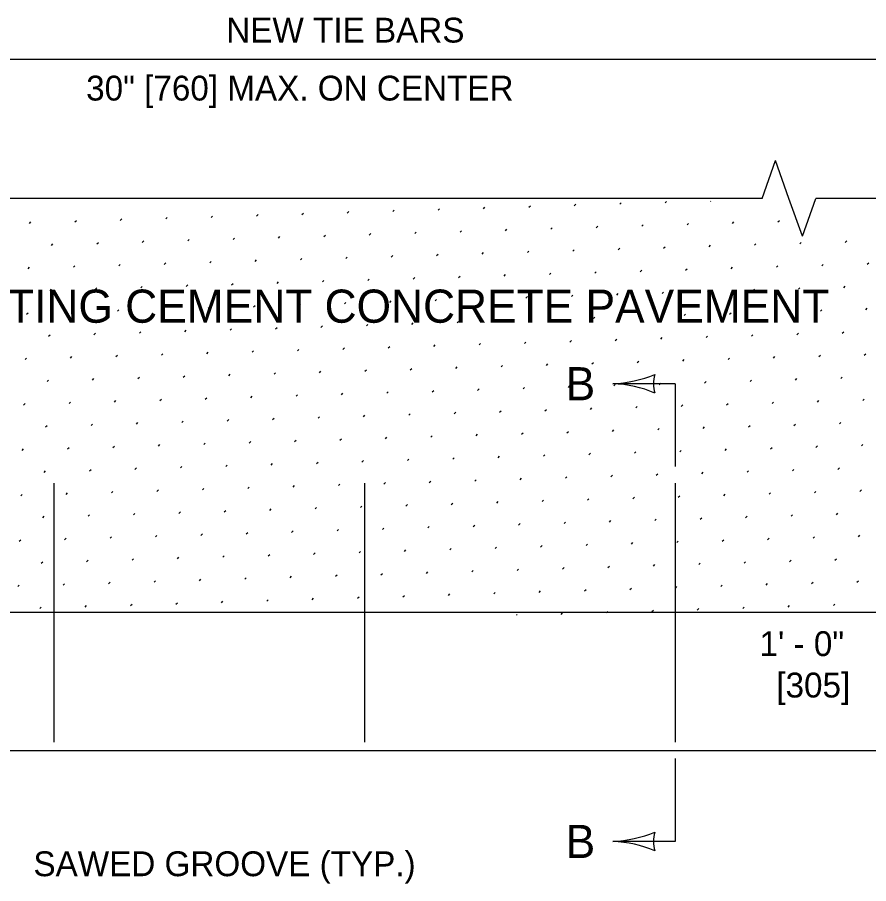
# Model space of a CAD drawing. Extents: x 49991.4 to 50021, y 49987.6 to 50011.4.
# Drawn here: x 50003.394 to 50005.45, y 49991.149 to 49993.241 of the extents above; entities that cross this region are included whole.
import ezdxf

# ---------------------------------------------------------------- set-up
doc = ezdxf.new("R2010")
doc.units = 0
for name, color, linetype in [('Level 1', 7, 'Continuous'), ('Level 10', 7, 'Continuous'), ('Level 2', 7, 'Continuous'), ('Level 3', 7, 'Continuous'), ('Level 4', 7, 'Continuous'), ('Level 6', 7, 'Continuous')]:
    doc.layers.add(name, color=color, linetype=linetype)

msp = doc.modelspace()

# ---------------------------------------------------------------- linework, layer by layer
at = {"layer": 'Level 1'}
for p, q in [((50006.1071, 49991.8039), (50002.3571, 49991.8039)), ((50002.6071, 49991.4706), (50005.8571, 49991.4706))]:
    msp.add_line(p, q, dxfattribs=at)
at = {"layer": 'Level 10'}
for p, q in [((50004.9581, 49992.793), (50004.9616, 49992.7966)), ((50005.0677, 49992.7966), (50005.0686, 49992.7974)), ((50004.3005, 49992.7718), (50004.304, 49992.7753)), ((50004.4101, 49992.7753), (50004.4136, 49992.7788)), ((50004.5197, 49992.7789), (50004.5232, 49992.7824)), ((50004.6293, 49992.7824), (50004.6328, 49992.7859)), ((50004.7389, 49992.7859), (50004.7424, 49992.7895)), ((50004.8485, 49992.7895), (50004.852, 49992.793)), ((50003.6428, 49992.7505), (50003.6463, 49992.7541)), ((50003.7524, 49992.7541), (50003.7559, 49992.7576)), ((50003.862, 49992.7576), (50003.8656, 49992.7611)), ((50003.9716, 49992.7611), (50003.9752, 49992.7647)), ((50004.0812, 49992.7647), (50004.0848, 49992.7682)), ((50004.1908, 49992.7682), (50004.1944, 49992.7718)), ((50003.4236, 49992.7434), (50003.4271, 49992.747)), ((50003.5332, 49992.747), (50003.5367, 49992.7505)), ((50004.7919, 49992.7329), (50004.7955, 49992.7364)), ((50004.9015, 49992.7365), (50004.9051, 49992.74)), ((50005.0111, 49992.74), (50005.0147, 49992.7435)), ((50005.1207, 49992.7435), (50005.1243, 49992.7471)), ((50005.2304, 49992.7471), (50005.2339, 49992.7506)), ((50004.1343, 49992.7117), (50004.1378, 49992.7152)), ((50004.2439, 49992.7152), (50004.2474, 49992.7187)), ((50004.3535, 49992.7187), (50004.357, 49992.7223)), ((50004.4631, 49992.7223), (50004.4666, 49992.7258)), ((50004.5727, 49992.7258), (50004.5762, 49992.7294)), ((50004.6823, 49992.7294), (50004.6858, 49992.7329)), ((50003.4766, 49992.6904), (50003.4802, 49992.6939)), ((50003.5862, 49992.6939), (50003.5898, 49992.6975)), ((50003.6958, 49992.6975), (50003.6994, 49992.701)), ((50003.8054, 49992.701), (50003.809, 49992.7046)), ((50003.9151, 49992.7046), (50003.9186, 49992.7081)), ((50004.0247, 49992.7081), (50004.0282, 49992.7116)), ((50005.1738, 49992.6905), (50005.1773, 49992.694)), ((50005.2834, 49992.694), (50005.2869, 49992.6976)), ((50005.393, 49992.6976), (50005.3965, 49992.7011)), ((50004.5161, 49992.6692), (50004.5197, 49992.6728)), ((50004.6257, 49992.6728), (50004.6293, 49992.6763)), ((50004.7353, 49992.6763), (50004.7389, 49992.6799)), ((50004.845, 49992.6799), (50004.8485, 49992.6834)), ((50004.9546, 49992.6834), (50004.9581, 49992.687)), ((50005.0642, 49992.687), (50005.0677, 49992.6905)), ((50003.8585, 49992.648), (50003.862, 49992.6515)), ((50003.9681, 49992.6515), (50003.9716, 49992.6551)), ((50004.0777, 49992.6551), (50004.0812, 49992.6586)), ((50004.1873, 49992.6586), (50004.1908, 49992.6622)), ((50004.2969, 49992.6622), (50004.3004, 49992.6657)), ((50004.4065, 49992.6657), (50004.4101, 49992.6692)), ((50003.42, 49992.6338), (50003.4236, 49992.6374)), ((50003.5297, 49992.6374), (50003.5332, 49992.6409)), ((50003.6393, 49992.6409), (50003.6428, 49992.6444)), ((50003.7489, 49992.6444), (50003.7524, 49992.648)), ((50004.898, 49992.6268), (50004.9015, 49992.6304)), ((50005.0076, 49992.6304), (50005.0111, 49992.6339)), ((50005.1172, 49992.6339), (50005.1207, 49992.6375)), ((50005.2268, 49992.6375), (50005.2304, 49992.641)), ((50005.3364, 49992.641), (50005.34, 49992.6445)), ((50005.446, 49992.6446), (50005.4496, 49992.6481)), ((50004.2403, 49992.6056), (50004.2439, 49992.6091)), ((50004.3499, 49992.6091), (50004.3535, 49992.6127)), ((50004.4596, 49992.6127), (50004.4631, 49992.6162)), ((50004.5692, 49992.6162), (50004.5727, 49992.6198)), ((50004.6788, 49992.6198), (50004.6823, 49992.6233)), ((50004.7884, 49992.6233), (50004.7919, 49992.6268)), ((50003.5827, 49992.5843), (50003.5862, 49992.5879)), ((50003.6923, 49992.5879), (50003.6958, 49992.5914)), ((50003.8019, 49992.5914), (50003.8054, 49992.595)), ((50003.9115, 49992.595), (50003.915, 49992.5985)), ((50004.0211, 49992.5985), (50004.0247, 49992.602)), ((50004.1307, 49992.602), (50004.1343, 49992.6056)), ((50005.2798, 49992.5844), (50005.2834, 49992.588)), ((50005.3895, 49992.588), (50005.393, 49992.5915)), ((50003.4731, 49992.5808), (50003.4766, 49992.5843)), ((50004.6222, 49992.5632), (50004.6257, 49992.5667)), ((50004.7318, 49992.5667), (50004.7353, 49992.5703)), ((50004.8414, 49992.5703), (50004.8449, 49992.5738)), ((50004.951, 49992.5738), (50004.9546, 49992.5773)), ((50005.0606, 49992.5774), (50005.0642, 49992.5809)), ((50005.1702, 49992.5809), (50005.1738, 49992.5844)), ((50003.9645, 49992.5419), (50003.9681, 49992.5455)), ((50004.0742, 49992.5455), (50004.0777, 49992.549)), ((50004.1838, 49992.549), (50004.1873, 49992.5525)), ((50004.2934, 49992.5526), (50004.2969, 49992.5561)), ((50004.403, 49992.5561), (50004.4065, 49992.5596)), ((50004.5126, 49992.5596), (50004.5161, 49992.5632)), ((50003.4165, 49992.5242), (50003.42, 49992.5277)), ((50003.5261, 49992.5278), (50003.5296, 49992.5313)), ((50003.6357, 49992.5313), (50003.6393, 49992.5348)), ((50003.7453, 49992.5348), (50003.7489, 49992.5384)), ((50003.8549, 49992.5384), (50003.8585, 49992.5419)), ((50005.0041, 49992.5208), (50005.0076, 49992.5243)), ((50005.1137, 49992.5243), (50005.1172, 49992.5279)), ((50005.2233, 49992.5279), (50005.2268, 49992.5314)), ((50005.3329, 49992.5314), (50005.3364, 49992.5349)), ((50005.4425, 49992.5349), (50005.446, 49992.5385)), ((50004.3464, 49992.4995), (50004.3499, 49992.5031)), ((50004.456, 49992.5031), (50004.4595, 49992.5066)), ((50004.5656, 49992.5066), (50004.5692, 49992.5101)), ((50004.6752, 49992.5101), (50004.6788, 49992.5137)), ((50004.7848, 49992.5137), (50004.7884, 49992.5172)), ((50004.8944, 49992.5172), (50004.898, 49992.5208)), ((50003.7984, 49992.4818), (50003.8019, 49992.4853)), ((50003.908, 49992.4854), (50003.9115, 49992.4889)), ((50004.0176, 49992.4889), (50004.0211, 49992.4924)), ((50004.1272, 49992.4924), (50004.1307, 49992.496)), ((50004.2368, 49992.496), (50004.2403, 49992.4995)), ((50003.4695, 49992.4712), (50003.4731, 49992.4747)), ((50003.5791, 49992.4747), (50003.5827, 49992.4783)), ((50003.6888, 49992.4783), (50003.6923, 49992.4818)), ((50004.8379, 49992.4607), (50004.8414, 49992.4642)), ((50004.9475, 49992.4642), (50004.951, 49992.4677)), ((50005.0571, 49992.4677), (50005.0606, 49992.4713)), ((50005.1667, 49992.4713), (50005.1702, 49992.4748)), ((50005.2763, 49992.4748), (50005.2798, 49992.4784)), ((50005.3859, 49992.4784), (50005.3894, 49992.4819)), ((50004.1802, 49992.4394), (50004.1838, 49992.4429)), ((50004.2898, 49992.4429), (50004.2934, 49992.4465)), ((50004.3994, 49992.4465), (50004.403, 49992.45)), ((50004.509, 49992.45), (50004.5126, 49992.4536)), ((50004.6187, 49992.4536), (50004.6222, 49992.4571)), ((50004.7283, 49992.4571), (50004.7318, 49992.4607)), ((50003.5226, 49992.4181), (50003.5261, 49992.4217)), ((50003.6322, 49992.4217), (50003.6357, 49992.4252)), ((50003.7418, 49992.4252), (50003.7453, 49992.4288)), ((50003.8514, 49992.4288), (50003.8549, 49992.4323)), ((50003.961, 49992.4323), (50003.9645, 49992.4359)), ((50004.0706, 49992.4359), (50004.0741, 49992.4394)), ((50005.2197, 49992.4183), (50005.2233, 49992.4218)), ((50005.3293, 49992.4218), (50005.3329, 49992.4253)), ((50005.4389, 49992.4253), (50005.4425, 49992.4289)), ((50003.413, 49992.4146), (50003.4165, 49992.4181)), ((50004.5621, 49992.397), (50004.5656, 49992.4005)), ((50004.6717, 49992.4005), (50004.6752, 49992.4041)), ((50004.7813, 49992.4041), (50004.7848, 49992.4076)), ((50004.8909, 49992.4076), (50004.8944, 49992.4112)), ((50005.0005, 49992.4112), (50005.004, 49992.4147)), ((50005.1101, 49992.4147), (50005.1137, 49992.4182)), ((50003.9044, 49992.3757), (50003.908, 49992.3793)), ((50004.014, 49992.3793), (50004.0176, 49992.3828)), ((50004.1236, 49992.3828), (50004.1272, 49992.3864)), ((50004.2333, 49992.3864), (50004.2368, 49992.3899)), ((50004.3429, 49992.3899), (50004.3464, 49992.3934)), ((50004.4525, 49992.3935), (50004.456, 49992.397)), ((50003.466, 49992.3616), (50003.4695, 49992.3651)), ((50003.5756, 49992.3651), (50003.5791, 49992.3686)), ((50003.6852, 49992.3687), (50003.6887, 49992.3722)), ((50003.7948, 49992.3722), (50003.7984, 49992.3757)), ((50004.9439, 49992.3546), (50004.9475, 49992.3581)), ((50005.0535, 49992.3581), (50005.0571, 49992.3617)), ((50005.1632, 49992.3617), (50005.1667, 49992.3652)), ((50005.2728, 49992.3652), (50005.2763, 49992.3688)), ((50005.3824, 49992.3688), (50005.3859, 49992.3723)), ((50004.2863, 49992.3333), (50004.2898, 49992.3369)), ((50004.3959, 49992.3369), (50004.3994, 49992.3404)), ((50004.5055, 49992.3404), (50004.509, 49992.344)), ((50004.6151, 49992.344), (50004.6186, 49992.3475)), ((50004.7247, 49992.3475), (50004.7283, 49992.351)), ((50004.8343, 49992.351), (50004.8379, 49992.3546)), ((50003.6286, 49992.3121), (50003.6322, 49992.3156)), ((50003.7382, 49992.3156), (50003.7418, 49992.3192)), ((50003.8479, 49992.3192), (50003.8514, 49992.3227)), ((50003.9575, 49992.3227), (50003.961, 49992.3262)), ((50004.0671, 49992.3263), (50004.0706, 49992.3298)), ((50004.1767, 49992.3298), (50004.1802, 49992.3333)), ((50005.3258, 49992.3122), (50005.3293, 49992.3157)), ((50005.4354, 49992.3157), (50005.4389, 49992.3193)), ((50003.4094, 49992.305), (50003.413, 49992.3085)), ((50003.519, 49992.3085), (50003.5226, 49992.3121)), ((50004.6681, 49992.2909), (50004.6717, 49992.2945)), ((50004.7778, 49992.2945), (50004.7813, 49992.298)), ((50004.8874, 49992.298), (50004.8909, 49992.3016)), ((50004.997, 49992.3016), (50005.0005, 49992.3051)), ((50005.1066, 49992.3051), (50005.1101, 49992.3086)), ((50005.2162, 49992.3086), (50005.2197, 49992.3122)), ((50004.0105, 49992.2697), (50004.014, 49992.2732)), ((50004.1201, 49992.2732), (50004.1236, 49992.2768)), ((50004.2297, 49992.2768), (50004.2332, 49992.2803)), ((50004.3393, 49992.2803), (50004.3429, 49992.2838)), ((50004.4489, 49992.2838), (50004.4525, 49992.2874)), ((50004.5585, 49992.2874), (50004.5621, 49992.2909)), ((50003.4624, 49992.252), (50003.466, 49992.2555)), ((50003.5721, 49992.2555), (50003.5756, 49992.259)), ((50003.6817, 49992.259), (50003.6852, 49992.2626)), ((50003.7913, 49992.2626), (50003.7948, 49992.2661)), ((50003.9009, 49992.2661), (50003.9044, 49992.2697)), ((50005.05, 49992.2485), (50005.0535, 49992.2521)), ((50005.1596, 49992.2521), (50005.1631, 49992.2556)), ((50005.2692, 49992.2556), (50005.2728, 49992.2591)), ((50005.3788, 49992.2592), (50005.3824, 49992.2627)), ((50004.502, 49992.2308), (50004.5055, 49992.2343)), ((50004.6116, 49992.2344), (50004.6151, 49992.2379)), ((50004.7212, 49992.2379), (50004.7247, 49992.2414)), ((50004.8308, 49992.2414), (50004.8343, 49992.245)), ((50004.9404, 49992.245), (50004.9439, 49992.2485)), ((50003.8443, 49992.2096), (50003.8478, 49992.2131)), ((50003.9539, 49992.2131), (50003.9575, 49992.2166)), ((50004.0635, 49992.2166), (50004.0671, 49992.2202)), ((50004.1731, 49992.2202), (50004.1767, 49992.2237)), ((50004.2827, 49992.2237), (50004.2863, 49992.2273)), ((50004.3924, 49992.2273), (50004.3959, 49992.2308)), ((50003.4059, 49992.1954), (50003.4094, 49992.1989)), ((50003.5155, 49992.1989), (50003.519, 49992.2025)), ((50003.6251, 49992.2025), (50003.6286, 49992.206)), ((50003.7347, 49992.206), (50003.7382, 49992.2096)), ((50004.8838, 49992.1884), (50004.8874, 49992.1919)), ((50004.9934, 49992.192), (50004.997, 49992.1955)), ((50005.103, 49992.1955), (50005.1066, 49992.199)), ((50005.2126, 49992.199), (50005.2162, 49992.2026)), ((50005.3223, 49992.2026), (50005.3258, 49992.2061)), ((50005.4319, 49992.2061), (50005.4354, 49992.2097)), ((50004.2262, 49992.1672), (50004.2297, 49992.1707)), ((50004.3358, 49992.1707), (50004.3393, 49992.1742)), ((50004.4454, 49992.1742), (50004.4489, 49992.1778)), ((50004.555, 49992.1778), (50004.5585, 49992.1813)), ((50004.6646, 49992.1813), (50004.6681, 49992.1849)), ((50004.7742, 49992.1849), (50004.7777, 49992.1884)), ((50003.5685, 49992.1459), (50003.5721, 49992.1494)), ((50003.6781, 49992.1494), (50003.6817, 49992.153)), ((50003.7877, 49992.153), (50003.7913, 49992.1565)), ((50003.8973, 49992.1565), (50003.9009, 49992.1601)), ((50004.0069, 49992.1601), (50004.0105, 49992.1636)), ((50004.1166, 49992.1636), (50004.1201, 49992.1671)), ((50005.2657, 49992.146), (50005.2692, 49992.1495)), ((50005.3753, 49992.1495), (50005.3788, 49992.1531)), ((50003.4589, 49992.1424), (50003.4624, 49992.1459)), ((50004.608, 49992.1247), (50004.6116, 49992.1283)), ((50004.7176, 49992.1283), (50004.7212, 49992.1318)), ((50004.8272, 49992.1318), (50004.8308, 49992.1354)), ((50004.9369, 49992.1354), (50004.9404, 49992.1389)), ((50005.0465, 49992.1389), (50005.05, 49992.1425)), ((50005.1561, 49992.1425), (50005.1596, 49992.146)), ((50003.9504, 49992.1035), (50003.9539, 49992.107)), ((50004.06, 49992.107), (50004.0635, 49992.1106)), ((50004.1696, 49992.1106), (50004.1731, 49992.1141)), ((50004.2792, 49992.1141), (50004.2827, 49992.1177)), ((50004.3888, 49992.1177), (50004.3923, 49992.1212)), ((50004.4984, 49992.1212), (50004.502, 49992.1247)), ((50003.4023, 49992.0858), (50003.4059, 49992.0893)), ((50003.5119, 49992.0893), (50003.5155, 49992.0929)), ((50003.6215, 49992.0929), (50003.6251, 49992.0964)), ((50003.7312, 49992.0964), (50003.7347, 49992.0999)), ((50003.8408, 49992.0999), (50003.8443, 49992.1035)), ((50004.9899, 49992.0823), (50004.9934, 49992.0859)), ((50005.0995, 49992.0859), (50005.103, 49992.0894)), ((50005.2091, 49992.0894), (50005.2126, 49992.093)), ((50005.3187, 49992.093), (50005.3222, 49992.0965)), ((50005.4283, 49992.0965), (50005.4319, 49992.1)), ((50004.3322, 49992.0611), (50004.3358, 49992.0646)), ((50004.4418, 49992.0646), (50004.4454, 49992.0682)), ((50004.5515, 49992.0682), (50004.555, 49992.0717)), ((50004.6611, 49992.0717), (50004.6646, 49992.0752)), ((50004.7707, 49992.0753), (50004.7742, 49992.0788)), ((50004.8803, 49992.0788), (50004.8838, 49992.0823)), ((50003.6746, 49992.0398), (50003.6781, 49992.0434)), ((50003.7842, 49992.0434), (50003.7877, 49992.0469)), ((50003.8938, 49992.0469), (50003.8973, 49992.0505)), ((50004.0034, 49992.0505), (50004.0069, 49992.054)), ((50004.113, 49992.054), (50004.1166, 49992.0575)), ((50004.2226, 49992.0575), (50004.2262, 49992.0611)), ((50005.3717, 49992.0399), (50005.3753, 49992.0435)), ((50003.4554, 49992.0327), (50003.4589, 49992.0363)), ((50003.565, 49992.0363), (50003.5685, 49992.0398)), ((50004.7141, 49992.0187), (50004.7176, 49992.0222)), ((50004.8237, 49992.0222), (50004.8272, 49992.0258)), ((50004.9333, 49992.0258), (50004.9368, 49992.0293)), ((50005.0429, 49992.0293), (50005.0465, 49992.0328)), ((50005.1525, 49992.0329), (50005.1561, 49992.0364)), ((50005.2621, 49992.0364), (50005.2657, 49992.0399)), ((50004.166, 49992.001), (50004.1696, 49992.0045)), ((50004.2757, 49992.0045), (50004.2792, 49992.008)), ((50004.3853, 49992.0081), (50004.3888, 49992.0116)), ((50004.4949, 49992.0116), (50004.4984, 49992.0151)), ((50004.6045, 49992.0151), (50004.608, 49992.0187)), ((50003.5084, 49991.9797), (50003.5119, 49991.9832)), ((50003.618, 49991.9833), (50003.6215, 49991.9868)), ((50003.7276, 49991.9868), (50003.7311, 49991.9903)), ((50003.8372, 49991.9903), (50003.8408, 49991.9939)), ((50003.9468, 49991.9939), (50003.9504, 49991.9974)), ((50004.0564, 49991.9974), (50004.06, 49992.001)), ((50005.2056, 49991.9798), (50005.2091, 49991.9834)), ((50005.3152, 49991.9834), (50005.3187, 49991.9869)), ((50005.4248, 49991.9869), (50005.4283, 49991.9904)), ((50003.3988, 49991.9762), (50003.4023, 49991.9797)), ((50004.5479, 49991.9586), (50004.5514, 49991.9621)), ((50004.6575, 49991.9621), (50004.6611, 49991.9656)), ((50004.7671, 49991.9656), (50004.7707, 49991.9692)), ((50004.8767, 49991.9692), (50004.8803, 49991.9727)), ((50004.9863, 49991.9727), (50004.9899, 49991.9763)), ((50005.096, 49991.9763), (50005.0995, 49991.9798)), ((50003.8903, 49991.9373), (50003.8938, 49991.9408)), ((50003.9999, 49991.9409), (50004.0034, 49991.9444)), ((50004.1095, 49991.9444), (50004.113, 49991.9479)), ((50004.2191, 49991.9479), (50004.2226, 49991.9515)), ((50004.3287, 49991.9515), (50004.3322, 49991.955)), ((50004.4383, 49991.955), (50004.4418, 49991.9586)), ((50003.4518, 49991.9231), (50003.4554, 49991.9267)), ((50003.5614, 49991.9267), (50003.565, 49991.9302)), ((50003.671, 49991.9302), (50003.6746, 49991.9338)), ((50003.7806, 49991.9338), (50003.7842, 49991.9373)), ((50004.9298, 49991.9162), (50004.9333, 49991.9197)), ((50005.0394, 49991.9197), (50005.0429, 49991.9232)), ((50005.149, 49991.9232), (50005.1525, 49991.9268)), ((50005.2586, 49991.9268), (50005.2621, 49991.9303)), ((50005.3682, 49991.9303), (50005.3717, 49991.9339)), ((50004.2721, 49991.8949), (50004.2757, 49991.8984)), ((50004.3817, 49991.8984), (50004.3853, 49991.902)), ((50004.4913, 49991.902), (50004.4949, 49991.9055)), ((50004.6009, 49991.9055), (50004.6045, 49991.9091)), ((50004.7105, 49991.9091), (50004.7141, 49991.9126)), ((50004.8202, 49991.9126), (50004.8237, 49991.9162)), ((50003.6145, 49991.8736), (50003.618, 49991.8772)), ((50003.7241, 49991.8772), (50003.7276, 49991.8807)), ((50003.8337, 49991.8807), (50003.8372, 49991.8843)), ((50003.9433, 49991.8843), (50003.9468, 49991.8878)), ((50004.0529, 49991.8878), (50004.0564, 49991.8914)), ((50004.1625, 49991.8914), (50004.166, 49991.8949)), ((50005.3116, 49991.8738), (50005.3152, 49991.8773)), ((50005.4212, 49991.8773), (50005.4248, 49991.8808)), ((50003.3952, 49991.8666), (50003.3988, 49991.8701)), ((50003.5049, 49991.8701), (50003.5084, 49991.8736)), ((50004.654, 49991.8525), (50004.6575, 49991.856)), ((50004.7636, 49991.856), (50004.7671, 49991.8596)), ((50004.8732, 49991.8596), (50004.8767, 49991.8631)), ((50004.9828, 49991.8631), (50004.9863, 49991.8667)), ((50005.0924, 49991.8667), (50005.0959, 49991.8702)), ((50005.202, 49991.8702), (50005.2056, 49991.8737)), ((50003.9963, 49991.8312), (50003.9999, 49991.8348)), ((50004.1059, 49991.8348), (50004.1095, 49991.8383)), ((50004.2155, 49991.8383), (50004.2191, 49991.8419)), ((50004.3251, 49991.8419), (50004.3287, 49991.8454)), ((50004.4348, 49991.8454), (50004.4383, 49991.8489)), ((50004.5444, 49991.849), (50004.5479, 49991.8525)), ((50003.4483, 49991.8135), (50003.4518, 49991.8171)), ((50003.5579, 49991.8171), (50003.5614, 49991.8206)), ((50003.6675, 49991.8206), (50003.671, 49991.8241)), ((50003.7771, 49991.8242), (50003.7806, 49991.8277)), ((50003.8867, 49991.8277), (50003.8902, 49991.8312)), ((50005.0358, 49991.8101), (50005.0394, 49991.8136)), ((50005.1454, 49991.8136), (50005.149, 49991.8172)), ((50005.255, 49991.8172), (50005.2586, 49991.8207)), ((50005.3647, 49991.8207), (50005.3682, 49991.8243)), ((50004.5989, 49991.7974), (50004.6009, 49991.7995)), ((50004.707, 49991.7995), (50004.7105, 49991.803)), ((50004.8166, 49991.803), (50004.8202, 49991.8065)), ((50004.9262, 49991.8065), (50004.9298, 49991.8101))]:
    msp.add_line(p, q, dxfattribs=at)
at = {"layer": 'Level 3'}
msp.add_line((50002.7321, 49993.14), (50005.7321, 49993.14), dxfattribs=at)
for centre, radius, start, end in [((50004.8167, 49992.6667), 0.3107, 272.8273, 292.0772), ((50005.003, 49992.3564), 0.073, 162.1388, 197.8612), ((50004.8199, 49992.0602), 0.2964, 67.456, 87.6395), ((50004.8167, 49991.5617), 0.3107, 272.8273, 292.0772), ((50005.003, 49991.2514), 0.073, 162.1388, 197.8612), ((50004.8199, 49990.9552), 0.2964, 67.456, 87.6395)]:
    msp.add_arc(centre, radius, start, end, dxfattribs=at)
at = {"layer": 'Level 4'}
for p, q in [((50003.4821, 49992.1164), (50003.4821, 49991.4914)), ((50004.2321, 49992.1164), (50004.2321, 49991.4914)), ((50004.9821, 49992.1164), (50004.9821, 49991.4914))]:
    msp.add_line(p, q, dxfattribs=at)
at = {"layer": 'Level 6'}
for p, q in [((50005.1923, 49992.8039), (50005.2247, 49992.8953)), ((50005.2571, 49992.8039), (50005.2247, 49992.8953)), ((50005.1923, 49992.8039), (50003.2719, 49992.8039)), ((50005.2895, 49992.7125), (50005.2571, 49992.8039)), ((50005.2895, 49992.7125), (50005.3219, 49992.8039)), ((50007.4071, 49992.8039), (50005.3219, 49992.8039)), ((50004.9821, 49992.3564), (50004.8321, 49992.3564)), ((50004.9821, 49992.3564), (50004.9821, 49992.1564)), ((50004.9821, 49991.4514), (50004.9821, 49991.2514)), ((50004.9821, 49991.2514), (50004.8321, 49991.2514))]:
    msp.add_line(p, q, dxfattribs=at)

# ---------------------------------------------------------------- texts
at = {"layer": 'Level 2'}
for s, height, p in [('NEW TIE BARS', 0.06, (50003.8986, 49993.18)), ('30" [760] MAX. ON CENTER', 0.06, (50003.5603, 49993.04)), ('EXISTING CEMENT CONCRETE PAVEMENT', 0.08, (50003.1255, 49992.5036)), ('B', 0.08, (50004.718, 49992.3164)), ('1\' - 0"', 0.06, (50005.186, 49991.6989)), ('[305]', 0.06, (50005.2266, 49991.5989)), ('B', 0.08, (50004.718, 49991.2114)), ('SAWED GROOVE (TYP.)', 0.06, (50003.433, 49991.1675))]:
    msp.add_text(s, height=height, dxfattribs=at).set_placement(p)

doc.saveas('drawing.dxf')
